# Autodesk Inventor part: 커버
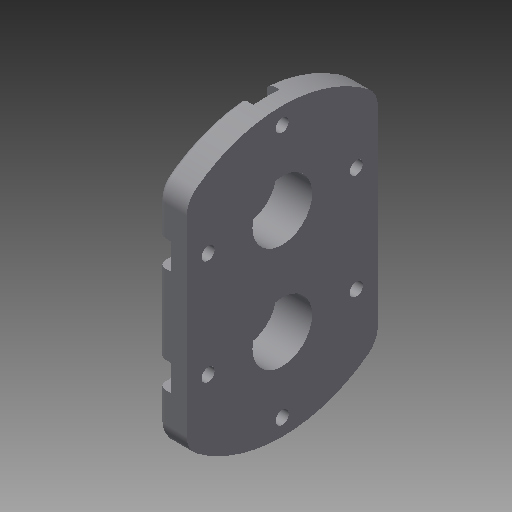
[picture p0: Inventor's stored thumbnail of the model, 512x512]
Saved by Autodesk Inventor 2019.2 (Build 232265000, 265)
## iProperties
Created: 2019-03
Part Number: 커버
Material: 알루미늄 6061
Document SubType Name: Modeling
Designer: mduedu
Density: 1 g/cm^3
Appearance: 기본값
Author: mduedu
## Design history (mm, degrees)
sketch "스케치1"
  geometry: L1 (44.721, -40)-(-44.721, -40); L2 (44.721, 40)-(-44.721, 40); A1 r 60 centre (0, 0) between (44.721, -40) and (44.721, 40); A2 r 60 centre (0, 0) between (-44.721, 40) and (-44.721, -40); 5 further points
  constraints: 6 point on circle, 4 end point, 2 centre point, 2 coincident, 2 horizontal alignment, 2 midpoint, 2 vertical alignment, 1 horizontal, 1 parallel
  dimensions: "d0" = 60 radius of A1; "d2" = 80 distance between parallel lines of L2 L1; "d3" = 120 distance of point (-60, 0) point (60, 0) (derived)
extrude "돌출1" new body sketch "스케치1" distance "d4" = 12; taper "d5" = 0 deg
sketch "스케치2"
  geometry: L1 (-20, -22)-(20, -22); L2 (20, -22)-(20, 22); L3 (20, 22)-(-20, 22); L4 (-20, 22)-(-20, -22); L5 (-20, -22)-(20, 22); L6 (20, -22)-(-20, 22); 3 further points
  constraints: 12 end point, 4 midpoint, 2 horizontal alignment, 2 parallel, 1 horizontal, 1 perpendicular, 4 other
  dimensions: "d6" = 40 distance between parallel lines of L2 L4; "d8" = 44 distance between parallel lines of L1 L3
extrude "돌출2" join sketch "스케치2" distance "d9" = 10; taper "d10" = 0 deg
fillet "모깎기1" dims "d11" = 10
fillet "모깎기2" dims "d12" = 3
sketch "스케치3"
  geometry: L1 (31, -22)-(31, 22); L2 (-31, 22)-(-31, -22); L3 (-31, -22)-(31, 22); L4 (31, -22)-(-31, 22); A1 r 31 centre (0, 22) between (31, 22) and (-31, 22); A2 r 31 centre (0, -22) between (-31, -22) and (31, -22); 7 further points
  constraints: 8 end point, 6 point on circle, 4 coincident, 3 tangent, 2 centre point, 2 midpoint, 1 parallel, 1 vertical, 1 vertical alignment
  dimensions: "d13" = 31 radius of A1; "d15" = 44 distance of A2.centre A1.centre
hole "구멍2" sketch "스케치3" at (-31, 22), (-31, -22), (31, -22), (31, 22), (0, 53), (0, -53) diameter "d28" = 5.5; stored, may be unused: countersink angle "d32" = 90 deg, drill point angle "d34" = 118 deg; dims "d29" = 6, "d30" = 4, "d31" = 2, "d33" = 8
sketch "스케치5"
  geometry: L1 (-40, 40)-(-40, -40) reference; L2 (40, -40)-(40, 40) reference; L3 (-5.5, 53)-(-5.5, 59.747); L4 (5.5, 53)-(5.5, 59.747); L5 (-31, 27.5)-(-40, 27.5); L6 (-31, 16.5)-(-40, 16.5); L7 (-31, -16.5)-(-40, -16.5); L8 (-31, -27.5)-(-40, -27.5); L9 (-5.5, -53)-(-5.5, -59.747); L10 (5.5, -53)-(5.5, -59.747); L11 (31, -27.5)-(40, -27.5); L12 (31, -16.5)-(40, -16.5); L13 (31, 16.5)-(40, 16.5); L14 (31, 27.5)-(40, 27.5); C1 r 2.75 at (0, 53) reference; C2 r 2.75 at (-31, 22) reference; C3 r 2.75 at (-31, -22) reference; C4 r 2.75 at (0, -53) reference; C5 r 2.75 at (31, -22) reference; C6 r 2.75 at (31, 22) reference; A1 r 60 centre (0, 0) between (36, 48) and (-36, 48) reference; A2 r 10 centre (-30, 40) between (-36, 48) and (-40, 40) reference; A3 r 10 centre (-30, -40) between (-40, -40) and (-36, -48) reference; A4 r 60 centre (0, 0) between (-36, -48) and (36, -48) reference; A5 r 10 centre (30, -40) between (36, -48) and (40, -40) reference; A6 r 10 centre (30, 40) between (40, 40) and (36, 48) reference; A7 r 5.5 centre (0, 53) between (-5.5, 53) and (5.5, 53); A8 r 5.5 centre (-31, 22) between (-31, 16.5) and (-31, 27.5); A9 r 5.5 centre (-31, -22) between (-31, -27.5) and (-31, -16.5); A10 r 5.5 centre (0, -53) between (5.5, -53) and (-5.5, -53); A11 r 5.5 centre (31, -22) between (31, -16.5) and (31, -27.5); A12 r 5.5 centre (31, 22) between (31, 27.5) and (31, 16.5); 1 further point
  constraints: 24 end point, 16 point on circle, 12 tangent, 8 parallel, 8 point on line, 6 centre point, 5 concentric, 4 horizontal, 1 coincident, 1 vertical
  dimensions: "d35" = 11 diameter of A7; "d36" = 11 diameter of A8; "d37" = 11 diameter of A9; "d38" = 11 diameter of A10; "d39" = 11 diameter of A11; "d40" = 11 diameter of A12
extrude "돌출4" cut sketch "스케치5" distance "d41" = 5.4; taper "d42" = 0 deg
sketch "스케치6"
  geometry: C1 r 12.5 at (0, 22); 1 further point
  constraints: 1 centre point, 1 vertical alignment
  dimensions: "d43" = 25 diameter of C1; "d45" = 22 distance of C1.centre point (0, 0)
extrude "돌출5" cut sketch "스케치6" distance "d47" = 15; taper "d48" = 0 deg
node "솔리드1"
mirror "대칭1"
